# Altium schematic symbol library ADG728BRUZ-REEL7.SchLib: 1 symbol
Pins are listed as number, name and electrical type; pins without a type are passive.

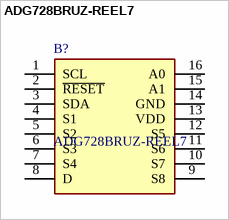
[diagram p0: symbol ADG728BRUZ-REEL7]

## ADG728BRUZ-REEL7
designator B?
Multiplexer Switch ICs SERIAL I2C, 8-ch MUX; Manufacturer_Name: Analog Devices; Geometry.Height: 1.2mm
footprint SOP65P640X120-16N
pins: 1 SCL, 2 ~{RESET}, 3 SDA, 4 S1, 5 S2, 6 S3, 7 S4, 8 D, 9 S8, 10 S7, 11 S6, 12 S5, 13 VDD, 14 GND, 15 A1, 16 A0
